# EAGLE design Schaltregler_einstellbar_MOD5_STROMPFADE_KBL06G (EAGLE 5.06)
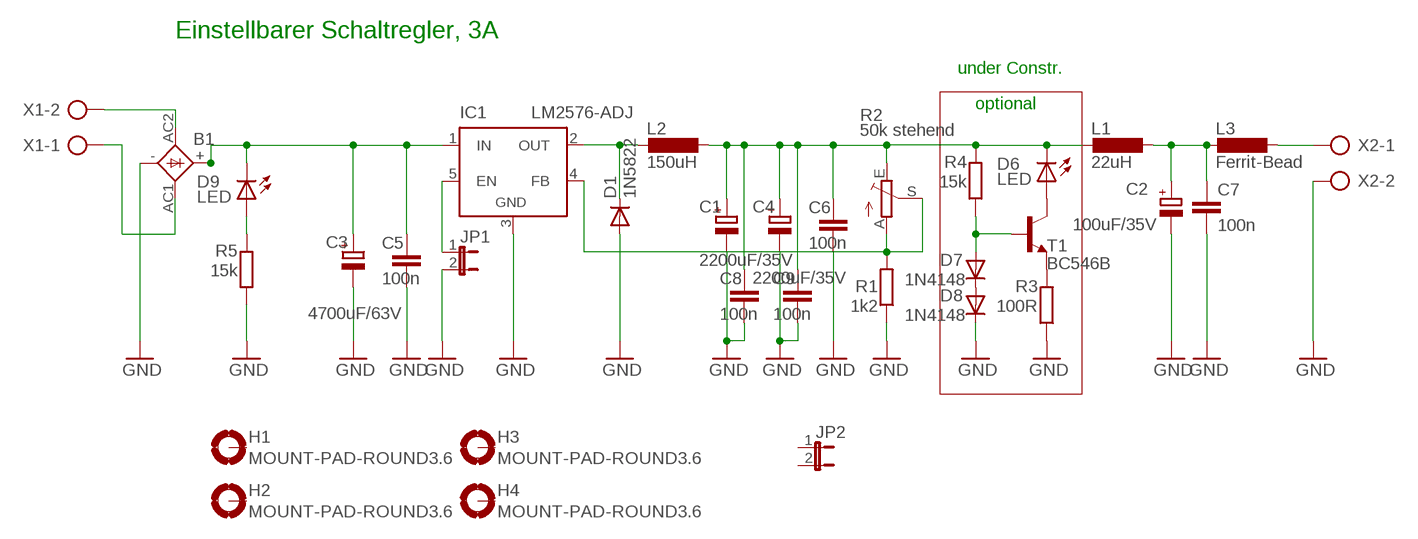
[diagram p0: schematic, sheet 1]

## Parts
B1  KBL  [KBL]
C1  2200uF/35V  CPOL-EUE7.5-16  [E7,5-16]
C2  100uF/35V  CPOL-EUE2.5-6  [E2,5-6]
C3  4700uF/63V  CPOL-EUE10-22.5  [EB22,5D]
C4  2200uF/35V  CPOL-EUE7.5-16  [E7,5-16]
C5  100n  C-EU025-024X044  [C025-024X044]
C6  100n  C-EU025-024X044  [C025-024X044]
C7  100n  C-EUC0805  [C0805]
C8  100n  C-EUC0805  [C0805]
C9  100n  C-EUC0805  [C0805]
D1  1N5822  BYW80  [TO220ACS]
D6  LED  LED5MM  [LED5MM]
D7  1N4148  1N4148DO35-7  [DO35-7]
D8  1N4148  1N4148DO35-7  [DO35-7]
D9  LED  LED5MM  [LED5MM]
H1  MOUNT-PAD-ROUND3.6  [3,6-PAD]
H2  MOUNT-PAD-ROUND3.6  [3,6-PAD]
H3  MOUNT-PAD-ROUND3.6  [3,6-PAD]
H4  MOUNT-PAD-ROUND3.6  [3,6-PAD]
IC1  LM2576-ADJ  LM2596TH  [TO220-52]
JP1  JP1E  [JP1]
JP2  JP1E  [JP1]
L1  22uH  L-EU2200-12.7  [2200-12.7]
L2  150uH  L-EUTJ5-U1  [TJ5-U1]
L3  Ferrit-Bead  L-EU0207/7  [0207/7]
R1  1k2  R-EU_0309/12  [0309/12]
R2  50k stehend  TRIM_EU-PT10S  [PT-10S]
R3  100R  R-EU_0207/7  [0207/7]
R4  15k  R-EU_0207/7  [0207/7]
R5  15k  R-EU_0207/7  [0207/7]
T1  BC546B  BC546A-NPN-TO92-EBC  [TO92-EBC]
X1  AK300/2  [AK300/2]
X2  AK300/2  [AK300/2]

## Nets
GND: B1.- C1.- C2.- C3.- C4.- C5.2 C6.2 C7.2 C8.2 C9.2 D1.A D8.C IC1.3(GND) JP1.2 R1.1 R3.1 R5.1 X2.2
N$1: D1.C IC1.2(OUT) L2.2
N$2: IC1.5(EN) JP1.1
N$5: B1.AC1(AC2) X1.1
N$6: B1.AC2(AC1) X1.2
N$7: L3.1 X2.1
N$9: C2.+ C7.1 L1.1 L3.2
N$12: D6.A T1.C
N$14: C1.+ C4.+ C6.1 C8.1 C9.1 D6.K(C) L1.2 L2.1 R2.E R4.2
N$15: D7.A R4.1 T1.B
N$16: B1.+ C3.+ C5.1 D9.K(C) IC1.1(IN)
N$17: R3.2 T1.E
N$18: D7.C D8.A
N$19: IC1.4(FB) R1.2 R2.A R2.S
N$22: D9.A R5.2
Unconnected: H1.B3,6(MOUNT) H2.B3,6(MOUNT) H3.B3,6(MOUNT) H4.B3,6(MOUNT) JP2.1 JP2.2

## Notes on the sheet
- Einstellbarer Schaltregler, 3A
- under Constr.
- optional

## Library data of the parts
B1 = rectifier:KBL: DIOTEC RECTIFIER
C1-C4 = rcl:CPOL-EU: POLARIZED CAPACITOR, European symbol
C5-C9 = resistor:C-EU: CAPACITOR, European symbol
D1 = diode:BYW80: DIODE
D6 D9 = led:LED: LED
D7 D8 = diode:1N4148: DIODE
H1-H4 = holes:MOUNT-PAD-ROUND: MOUNTING PAD, round
IC1 = linear:LM2596T: STEP-DOWN VOLTAGE REGULATOR
JP1 JP2 = jumper:JP1E: JUMPER
L1-L3 = rcl:L-EU: INDUCTOR, European symbol
R1 R3-R5 = rcl:R-EU_: RESISTOR, European symbol
R2 = pot:TRIM_EU-: POTENTIOMETER
T1 = transistor:*-NPN-: NPN Transistror BF959 corrected 2008.03.06
X1 X2 = con-ptr500:AK300/2: CONNECTOR

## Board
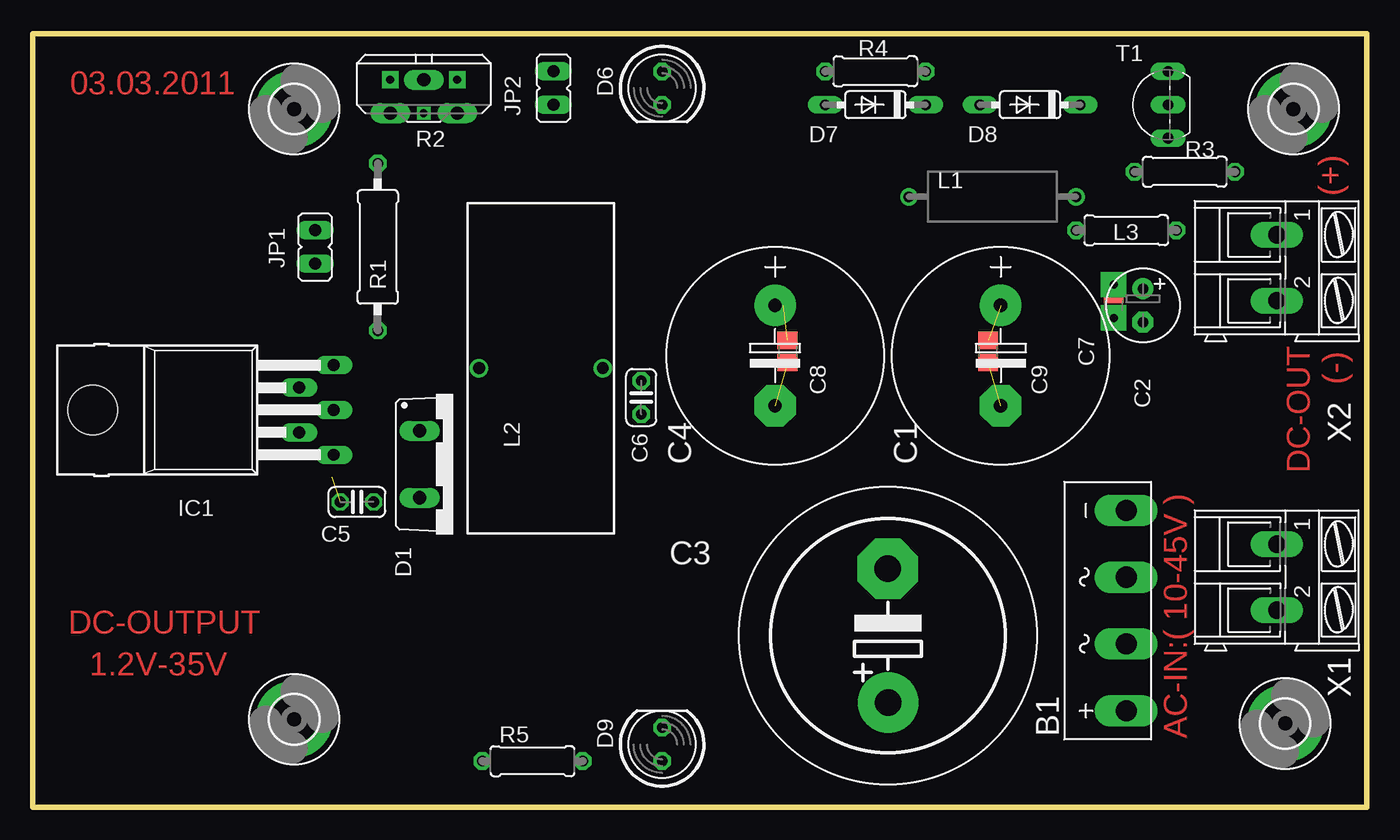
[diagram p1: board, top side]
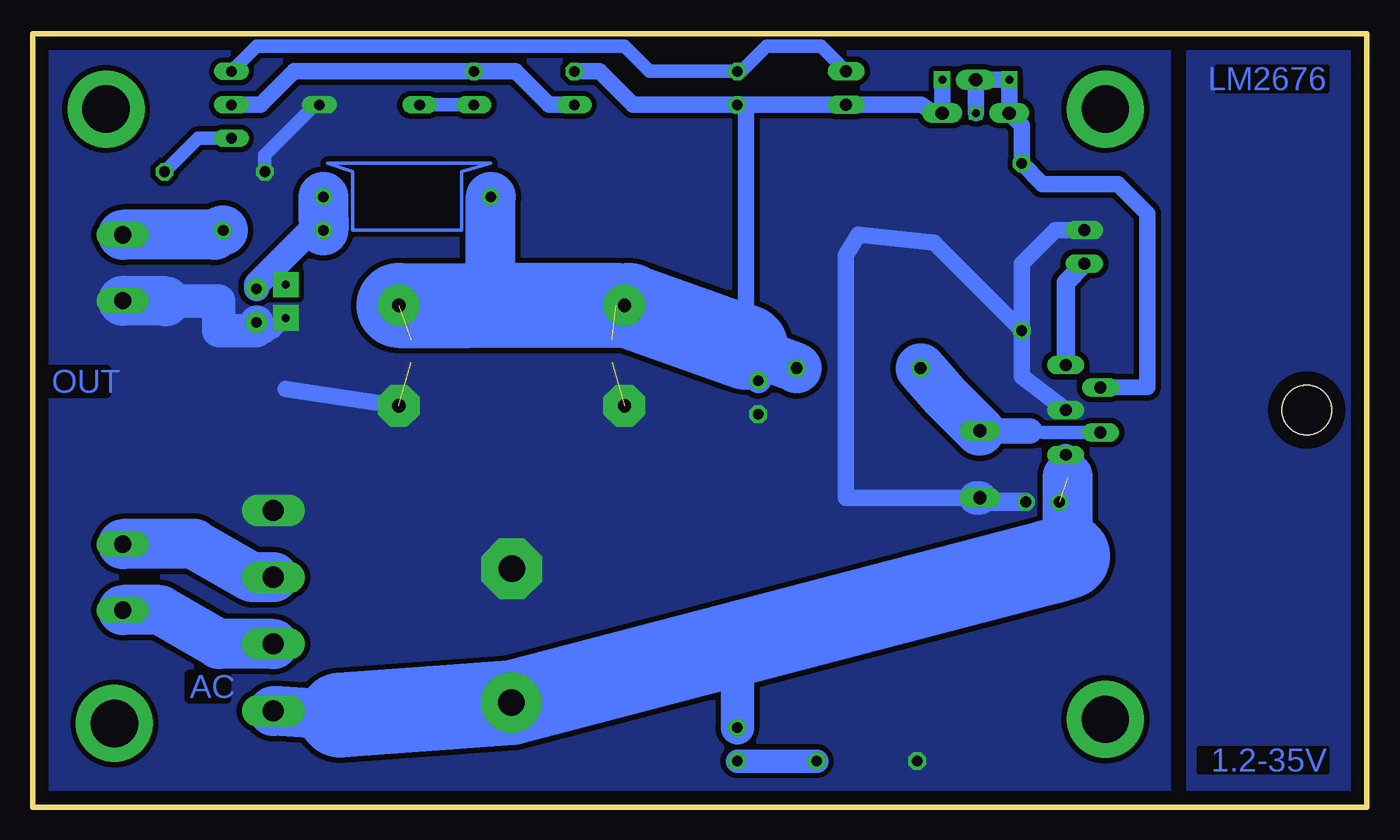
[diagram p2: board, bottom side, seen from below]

Size 101.27 x 58.73 mm. Coordinates in mm from the lower left corner, seen from the top.
Outline: 0,0 101.27,0 101.27,58.73 0,58.73 0,0
Copper layers (1*16): Top 0.035mm / dielectric 1.5mm / Bottom 0.035mm
Design rules "default": minimum track width 10mil, minimum drill 24mil, track to track 8mil, track to pad 8mil, pad to pad 8mil, via to via 8mil, smd to smd 8mil, copper to edge 40mil, drill to drill 8mil, minimum pad ring 10mil, minimum via ring 8mil, stop-mask expansion 4mil, vias tented up to drill 0mil, thermal gap 10mil

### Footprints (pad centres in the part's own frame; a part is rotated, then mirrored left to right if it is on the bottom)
KBL = drill 1.6 long: + -7.62,-1.27; - 7.62,-1.27; AC1 2.54,-1.27; AC2 -2.54,-1.27
E7,5-16 = drill 1.016 pad 3.15 round: + -3.81,0 | drill 1.016 pad 3.15 octagon: - 3.81,0
E2,5-6 = drill 0.813 pad 1.6 round: + -1.27,0 | drill 0.813 pad 1.6 octagon: - 1.27,0
EB22,5D = drill 2.007 pad 4.597 round: + -5.08,0 | drill 2.007 pad 4.597 octagon: - 5.08,0
C025-024X044 = drill 0.813 octagon: 1 -1.27,0; 2 1.27,0
C0805 = smd 1.3 x 1.5: 1 -0.85,0; 2 0.85,0
TO220ACS = drill 1.016 long: A 2.54,-2.54; C -2.54,-2.54
LED5MM = drill 0.813 octagon: A -1.27,0; K 1.27,0
DO35-7 = drill 0.813 long: A 3.81,0; C -3.81,0
3,6-PAD = drill 3.6 pad 5.842 round: B3,6 0,0
TO220-52 = drill 0.9 long: 1 -3.4,-21.1; 2 -1.7,-18.47; 3 0,-21.1; 4 1.7,-18.47; 5 3.4,-21.1 | hole 3.8: 0,-2.8
JP1 = drill 0.914 long: 1 0,-1.27; 2 0,1.27
2200-12.7 = drill 0.8 pad 1.27 round: 1 -6.35,0; 2 6.35,0
TJ5-U1 = drill 0.9 round: 1 -4.7,0; 2 4.7,0
0207/7 = drill 0.813 octagon: 1 -3.81,0; 2 3.81,0
0309/12 = drill 0.813 octagon: 1 -6.35,0; 2 6.35,0
PT-10S = drill 1.016 long: A -2.54,-1.27; E 2.54,-1.27; S 0,1.27
TO92-EBC = drill 0.813 long: B 0,-1.27; C 2.54,-1.27; E -2.54,-1.27
AK300/2 = drill 1.321 long: 1 -2.515,0; 2 2.489,0

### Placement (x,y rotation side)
B1  81.75,14.92 90 top
C1  73.49,34.28 270 top
C2  84.29,38.09 270 top
C3  64.92,13.01 90.1 top
C4  56.35,34.28 270 top
C5  24.6,23.17 0 top
C6  46.19,31.11 270 top
C7  82.07,38.09 270 top
C8  57.3,34.6 270 top
C9  72.54,34.6 270 top
D1  31.9,26.03 270 top
D6  47.78,54.61 270 top
D7  63.97,53.33 180 top
D8  75.72,53.33 180 top
D9  47.78,4.76 90 top
H1  95.72,53.02 0 top
H2  19.84,53.02 0 top
H3  95.08,6.34 0 top
H4  19.84,6.66 0 top
IC1  1.74,30.16 90 top
JP1  21.42,42.54 0 top
JP2  39.52,54.61 0 top
L1  72.86,46.35 180 top
L2  38.57,33.33 180 top
L3  83.02,43.81 180 top
R1  26.19,42.54 90 top
R2  29.68,53.97 0 top
R3  87.46,48.25 0 top
R4  63.97,55.88 180 top
R5  37.94,3.49 0 top
T1  84.92,53.33 90 top
X1  94.45,17.46 270 top
X2  94.45,40.95 270 top

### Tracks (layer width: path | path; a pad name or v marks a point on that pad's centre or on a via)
GND  (via drill 0.61 pad 1.93)  (2 unrouted)
  Top 1.27: C7.2 v82.07,37.14
  Bottom 1.016: R3.1 83.66,49.53 79.84,53.33 D8.C
  Bottom 1.27: JP1.2 23.65,43.81 26.19,41.27 R1.1 | IC1.3 26.19,32.7 R1.1 | R1.1 32.85,42.86 38.57,43.49 39.52,41.9 39.52,23.49 D1.A | C1.- 82.07,31.75 | v82.07,37.14 83.02,36.19 83.66,36.19
  Bottom 1.422: D1.A 28.73,23.17 C5.2
  Bottom 1.93: 83.66,36.19 C2.-
  Bottom 2.54: D1.A 29.68,23.49 | 91.22,38.41 87.15,38.41 87.15,36.19 84.29,36.19 C2.-
  Bottom 3.81: 91.22,38.41 X2.2
  pour Bottom (isolate 0.406, no thermals): 102.07,59.05 15.08,59.37 15.08,-0.64 102.07,-0.64
N$1
  Bottom 1.016: IC1.2 24.49,28.46 25.55,28.57
  Bottom 1.93: 25.55,28.57 D1.C
  Bottom 3.81: L2.2 31.96,31.17 D1.C
N$2
  Bottom 1.422: IC1.5 22.84,39.83 JP1.1
N$5
  Bottom 3.81: X1.1 89.05,20 84.61,17.46 B1.AC1
N$6
  Bottom 3.81: X1.2 91.64,14.97 87.15,12.38 B1.AC2
N$7
  Bottom 3.81: X2.1 87.49,43.47 L3.1
N$8
  pour Bottom: 13.49,59.05 13.49,-0.64 -0.8,-0.64 -0.8,59.05
N$9  (via drill 0.61 pad 1.93)
  Top 1.27: C7.1 v82.07,39.68
  Bottom 1.27: v82.07,39.68 83.18,40.79
  Bottom 1.93: C2.+ 84.29,39.68 83.18,40.79 79.21,44.76
  Bottom 3.81: L3.2 79.21,44.76 L1.1
N$12
  Bottom 1.016: T1.C 84.29,57.78 56.35,57.78 54.45,55.87 D6.A 47.46,55.87 45.55,57.78 41.43,57.78 39.52,55.87
N$13
  Bottom 0.254: 76.99,43.81 76.99,48.25 78.89,48.89 66.51,48.89 68.73,48.25 68.73,43.81 76.99,43.81
N$14  (via drill 0.61 pad 1.27)  (2 unrouted)
  Bottom 0.254: 47.62,35.09 47.14,36.82
  Bottom 1.27: 47.14,53.33 33.81,53.33 32.85,52.7 R2.E v32.22,55.24 | 47.14,36.82 47.14,53.33 | 47.14,53.33 D6.K 55.72,53.33 58.26,55.87 R4.2
  Bottom 1.93: 47.14,34.92 C6.1
  Bottom 3.81: 68.1,38.09 66.51,38.1 L1.2 | C1.+ 56.98,38.09 C4.+ 56.03,38.1 L2.1
  Bottom 6.452: C1.+ 68.1,38.09 56.98,38.09 | 56.03,38.1 47.62,35.09 47.14,34.92
N$15
  Bottom 1.27: D7.A 62.07,53.33 64.61,55.87 R4.1 81.43,55.87 83.97,53.33 T1.B
N$16  (1 unrouted)
  Bottom 0.254: 24.16,18.58 47.78,10.79
  Bottom 1.676: 22.69,25.08 IC1.1
  Bottom 2.54: 47.78,10.79 D9.K
  Bottom 3.81: 22.69,19.05 22.69,25.08 | 77.94,6.98 B1.+
  Bottom 6.452: 22.69,19.05 24.16,18.58 C3.+ 77.94,6.98
N$17
  Bottom 1.016: R3.2 88.73,50.79 T1.E
N$18
  Bottom 1.016: D7.C D8.A
N$19  (via drill 0.61, 0.61 pad 1.27)
  Bottom 1.27: IC1.4 16.66,31.91 16.66,45.08 18.88,47.3 24.6,47.3 R1.2 26.19,51.75 R2.A | R2.A 27.14,54.92 27.46,55.24 R2.S v29.68,52.7 | R2.A v27.14,55.24
N$22
  Bottom 1.778: R5.2 D9.A

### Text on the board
Top: 03.03.2011 | (+) | (-) | DC-OUT | AC-IN:( 10-45V ) | DC-OUTPUT | 1.2V-35V
Bottom: LM2676 | OUT | AC | 1.2-35V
